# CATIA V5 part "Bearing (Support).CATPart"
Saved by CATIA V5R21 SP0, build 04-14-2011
Part number: Bearing (Support)
Bounding box of the stored display mesh (mm): x -270 to 10, y -39.842 to 39.842, z -34.808 to 139.842
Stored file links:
  D:\CATIA V5R21 E-RESOURCES\CATIA-V5R21\catia-v5r21-Prts\c16_catia_v5r21_prt\Universal Joint-(Fig16-49)\Bearing (Support).CATPart
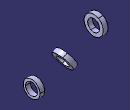
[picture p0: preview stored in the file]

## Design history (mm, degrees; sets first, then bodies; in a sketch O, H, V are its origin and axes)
Body1 (main body)
  Sketch1 on yz-plane, origin (0, 0, 0), H (0, 1, 0), V (0, 0, 1)
    circle A1 centre (0, 0) radius 25
    circle A2 centre (0, 0) radius 35
    radius A1 = 25
    radius A2 = 35
  Pad1: profile Sketch1, direction (1, 0, 0), length 10, mirrored extent
  Sketch2 on zx-plane, origin (0, 0, 0), H (-1, 0, 0), V (0, 0, 1)
    construction line L1 (0, 0) -> (60, 0)
    construction line L2 (60, 0) -> (194.1972, 77.4788)
    line L3 (107.5, 56.2917) -> (124.8205, 66.2917)
    line L4 (124.8205, 66.2917) -> (117.3205, 79.282)
    line L5 (117.3205, 79.282) -> (100, 69.282)
    point P6 (100, 69.282)
    line L6 (100, 69.282) -> (107.5, 56.2917)
    angle L2 L1 = 30
    distance L6 L4 = 20
    length L6 = 15
    distance L3 L2 = 25
    distance P6 V = 100
    length L1 = 60
    horizontal: L1 H
    perpendicularity: L4 L3
    parallelism: L5 L2, L6 L4
  Sketch3 on zx-plane, origin (0, 0, 0), H (-1, 0, 0), V (0, 0, 1)
    line L1 (60, 0) -> (221.9169, 93.4828)
    point P1 (60, 0)
    reference projected line E1 (107.5, 56.2917) -> (124.8205, 66.2917) from Sketch2.L3
    reference projected line E2 (107.5, 56.2917) -> (124.8205, 66.2917) from Sketch2.L3
    distance E2 L1 = 25
    coincidence: P1 H
    parallelism: L1 E1
  Shaft1: profile Sketch2, axis Sketch3.L1, angle 360
  Sketch4 on zx-plane, origin (0, 0, 0), H (-1, 0, 0), V (0, 0, 1)
    construction line L1 (188.3301, 100) -> (395.6544, 100)
    point P3 (260, 132.5)
    line L2 (270, 140) -> (270, 125)
    line L3 (270, 125) -> (250, 125)
    line L4 (250, 125) -> (250, 140)
    line L5 (250, 140) -> (270, 140)
    distance L1 H = 100
    length L5 = 20
    length L4 = 15
    distance L1 L3 = 25
    distance L4 V = 250
    horizontal: L1 H, L3 H, L5 H
    vertical: L2 V, L4 V
    equidistance: L2 L4 P3, L3 L5 P3
  Sketch5 on zx-plane, origin (0, 0, 0), H (-1, 0, 0), V (0, 0, 1)
    line L1 (210.3804, 100) -> (348.9415, 100)
    reference projected line E1 (250, 125) -> (270, 125) from Sketch4.L3
    distance L1 E1 = 25
    horizontal: L1 H
  Shaft2: profile Sketch4, axis Sketch5.L1, angle 360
